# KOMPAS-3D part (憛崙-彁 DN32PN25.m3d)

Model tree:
1. Объединить компоненты:1  (labels: СЕНС-ПР DN32PN25)

Referenced files in D:\Савин\!СЕНСОР\3D для заказчика\!Новый перечень\СЕНС-ПР\1. СЕНС-ПР\DN32\: СЕНС-ПР DN32PN25.a3d
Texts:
  СЕНС-ПР DN32PN25
  ООО НПП Сенсор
